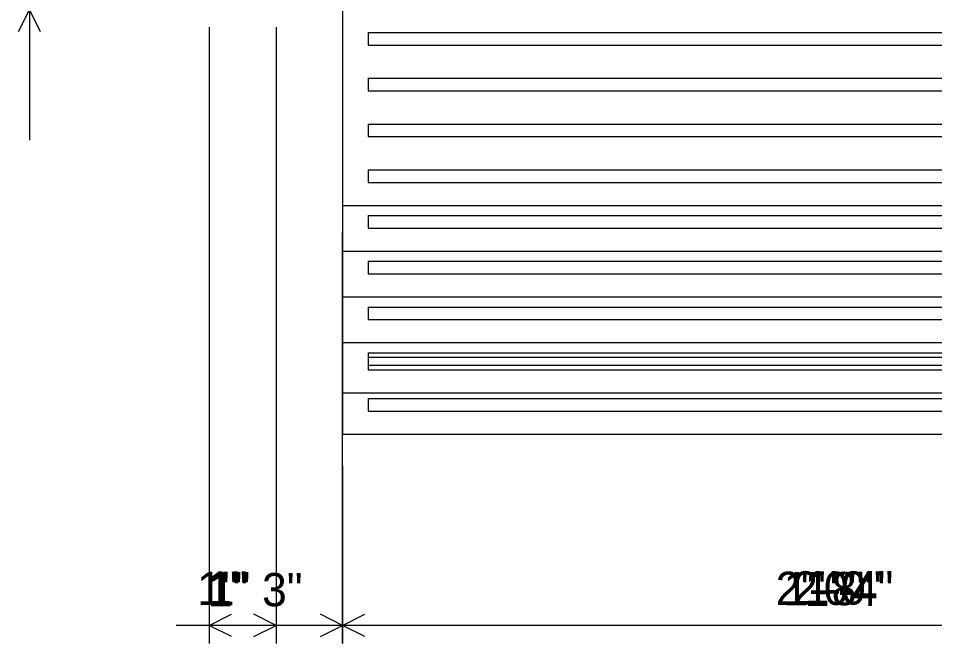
# Model space of a CAD drawing. Extents: x 997.7 to 1009.7, y 1494.3 to 1503.3.
# Drawn here: x 1000.466 to 1001.614, y 1499.262 to 1500.045 of the extents above; entities that cross this region are included whole.
import ezdxf

# ---------------------------------------------------------------- set-up
doc = ezdxf.new("R2010")
doc.units = 0
for name, color, linetype in [('Level 10', 7, 'Continuous'), ('Level 11', 7, 'Continuous'), ('Level 12', 7, 'Continuous'), ('Level 13', 7, 'Continuous'), ('Level 14', 7, 'Continuous'), ('Level 15', 7, 'Continuous'), ('Level 2', 7, 'Continuous'), ('Level 4', 7, 'Continuous'), ('Level 5', 7, 'Continuous'), ('Level 6', 7, 'Continuous'), ('Level 7', 7, 'Continuous'), ('Level 8', 7, 'Continuous'), ('Level 9', 7, 'Continuous')]:
    doc.layers.add(name, color=color, linetype=linetype)

msp = doc.modelspace()

# ---------------------------------------------------------------- linework, layer by layer
at = {"layer": 'Level 10'}
for p, q in [((1000.8725, 1499.9256), (1000.8725, 1499.7537)), ((1000.9044, 1499.7982), (1002.1738, 1499.7982)), ((1000.9044, 1499.7982), (1000.9044, 1499.7826)), ((1000.9044, 1499.7826), (1002.1738, 1499.7826)), ((1000.8725, 1499.7537), (1002.2058, 1499.7537)), ((1000.8725, 1499.2622), (1000.8725, 1499.7139))]:
    msp.add_line(p, q, dxfattribs=at)
at = {"layer": 'Level 11'}
for p, q in [((1000.8725, 1499.9256), (1000.8725, 1499.6964)), ((1000.9044, 1499.7982), (1002.1738, 1499.7982)), ((1000.9044, 1499.7982), (1000.9044, 1499.7826)), ((1000.9044, 1499.7826), (1002.1738, 1499.7826)), ((1000.9044, 1499.7409), (1002.1738, 1499.7409)), ((1000.9044, 1499.7409), (1000.9044, 1499.7253)), ((1000.9044, 1499.7253), (1002.1738, 1499.7253)), ((1000.8725, 1499.6964), (1002.2058, 1499.6964)), ((1000.8725, 1499.2622), (1000.8725, 1499.6591))]:
    msp.add_line(p, q, dxfattribs=at)
at = {"layer": 'Level 12'}
for p, q in [((1000.8725, 1499.9256), (1000.8725, 1499.6391)), ((1000.9044, 1499.7982), (1002.1738, 1499.7982)), ((1000.9044, 1499.7982), (1000.9044, 1499.7826)), ((1000.9044, 1499.7826), (1002.1738, 1499.7826)), ((1000.9044, 1499.7409), (1002.1738, 1499.7409)), ((1000.9044, 1499.7409), (1000.9044, 1499.7253)), ((1000.9044, 1499.7253), (1002.1738, 1499.7253)), ((1000.9044, 1499.6836), (1002.1738, 1499.6836)), ((1000.9044, 1499.6836), (1000.9044, 1499.668)), ((1000.9044, 1499.668), (1002.1738, 1499.668)), ((1000.8725, 1499.6391), (1002.2058, 1499.6391)), ((1000.8725, 1499.2622), (1000.8725, 1499.6085))]:
    msp.add_line(p, q, dxfattribs=at)
at = {"layer": 'Level 13'}
for p, q in [((1000.8725, 1499.9256), (1000.8725, 1499.5764)), ((1000.9044, 1499.7982), (1002.1738, 1499.7982)), ((1000.9044, 1499.7982), (1000.9044, 1499.7826)), ((1000.9044, 1499.7826), (1002.1738, 1499.7826)), ((1000.9044, 1499.7409), (1002.1738, 1499.7409)), ((1000.9044, 1499.7409), (1000.9044, 1499.7253)), ((1000.9044, 1499.7253), (1002.1738, 1499.7253)), ((1000.9044, 1499.6836), (1002.1738, 1499.6836)), ((1000.9044, 1499.6836), (1000.9044, 1499.668)), ((1000.9044, 1499.668), (1002.1738, 1499.668)), ((1000.9044, 1499.6208), (1002.1738, 1499.6208)), ((1000.9044, 1499.6208), (1000.9044, 1499.6052)), ((1000.9044, 1499.6052), (1002.1738, 1499.6052)), ((1000.8725, 1499.5764), (1002.2058, 1499.5764)), ((1000.8725, 1499.2622), (1000.8725, 1499.5413))]:
    msp.add_line(p, q, dxfattribs=at)
at = {"layer": 'Level 14'}
for p, q in [((1000.8725, 1499.9256), (1000.8725, 1499.5246)), ((1000.9044, 1499.7982), (1002.1738, 1499.7982)), ((1000.9044, 1499.7982), (1000.9044, 1499.7826)), ((1000.9044, 1499.7826), (1002.1738, 1499.7826)), ((1000.9044, 1499.7409), (1002.1738, 1499.7409)), ((1000.9044, 1499.7409), (1000.9044, 1499.7253)), ((1000.9044, 1499.7253), (1002.1738, 1499.7253)), ((1000.9044, 1499.6836), (1002.1738, 1499.6836)), ((1000.9044, 1499.6836), (1000.9044, 1499.668)), ((1000.9044, 1499.668), (1002.1738, 1499.668)), ((1000.9044, 1499.6263), (1002.1738, 1499.6263)), ((1000.9044, 1499.6263), (1000.9044, 1499.6107)), ((1000.9044, 1499.6107), (1002.1738, 1499.6107)), ((1000.9044, 1499.569), (1002.1738, 1499.569)), ((1000.9044, 1499.569), (1000.9044, 1499.5534)), ((1000.9044, 1499.5534), (1002.1738, 1499.5534)), ((1000.8725, 1499.5246), (1002.2058, 1499.5246)), ((1000.8725, 1499.4849), (1000.8725, 1499.2622))]:
    msp.add_line(p, q, dxfattribs=at)
at = {"layer": 'Level 15'}
for p, q in [((1000.7055, 1500.0341), (1000.7055, 1499.2622)), ((1000.8725, 1499.2851), (1000.7055, 1499.2851))]:
    msp.add_line(p, q, dxfattribs=at)
for points in [[(1000.7333, 1499.2712), (1000.7055, 1499.2851), (1000.7333, 1499.299)], [(1000.8448, 1499.2712), (1000.8725, 1499.2851), (1000.8448, 1499.299)]]:
    msp.add_lwpolyline(points, dxfattribs=at)
at = {"layer": 'Level 2'}
for p, q in [((1000.4803, 1500.0562), (1000.4803, 1499.8927)), ((1000.8725, 1500.0562), (1000.8725, 1499.9256)), ((1000.9044, 1500.0273), (1002.1738, 1500.0273)), ((1000.9044, 1500.0273), (1000.9044, 1500.0117)), ((1000.9044, 1500.0117), (1002.1738, 1500.0117)), ((1000.9044, 1499.9701), (1002.1738, 1499.9701)), ((1000.9044, 1499.9701), (1000.9044, 1499.9544)), ((1000.9044, 1499.9544), (1002.1738, 1499.9544)), ((1000.9044, 1499.9128), (1002.1738, 1499.9128)), ((1000.9044, 1499.9128), (1000.9044, 1499.8971)), ((1000.9044, 1499.8971), (1002.1738, 1499.8971)), ((1000.9044, 1499.8555), (1002.1738, 1499.8555)), ((1000.9044, 1499.8555), (1000.9044, 1499.8398)), ((1000.9044, 1499.8398), (1002.1738, 1499.8398)), ((1002.2058, 1499.2851), (1000.8725, 1499.2851))]:
    msp.add_line(p, q, dxfattribs=at)
for points in [[(1000.4942, 1500.0284), (1000.4803, 1500.0562), (1000.4663, 1500.0284)], [(1000.9003, 1499.2712), (1000.8725, 1499.2851), (1000.9003, 1499.299)]]:
    msp.add_lwpolyline(points, dxfattribs=at)
at = {"layer": 'Level 4'}
for p, q in [((1000.7892, 1500.0341), (1000.7892, 1499.2622)), ((1000.7892, 1499.2851), (1000.6642, 1499.2851))]:
    msp.add_line(p, q, dxfattribs=at)
msp.add_lwpolyline([(1000.7614, 1499.2712), (1000.7892, 1499.2851), (1000.7614, 1499.299)], dxfattribs=at)
at = {"layer": 'Level 5'}
for p, q in [((1000.7892, 1500.0341), (1000.7892, 1499.2622)), ((1000.7892, 1499.2851), (1000.6642, 1499.2851))]:
    msp.add_line(p, q, dxfattribs=at)
msp.add_lwpolyline([(1000.7614, 1499.2712), (1000.7892, 1499.2851), (1000.7614, 1499.299)], dxfattribs=at)
at = {"layer": 'Level 6'}
for p, q in [((1000.7892, 1500.0341), (1000.7892, 1499.2622)), ((1000.7892, 1499.2851), (1000.6642, 1499.2851))]:
    msp.add_line(p, q, dxfattribs=at)
msp.add_lwpolyline([(1000.7614, 1499.2712), (1000.7892, 1499.2851), (1000.7614, 1499.299)], dxfattribs=at)
at = {"layer": 'Level 7'}
for p, q in [((1000.7892, 1500.0341), (1000.7892, 1499.2622)), ((1000.7892, 1499.2851), (1000.6642, 1499.2851))]:
    msp.add_line(p, q, dxfattribs=at)
msp.add_lwpolyline([(1000.7614, 1499.2712), (1000.7892, 1499.2851), (1000.7614, 1499.299)], dxfattribs=at)
at = {"layer": 'Level 8'}
for p, q in [((1000.7892, 1500.0341), (1000.7892, 1499.2622)), ((1000.7892, 1499.2851), (1000.6642, 1499.2851))]:
    msp.add_line(p, q, dxfattribs=at)
msp.add_lwpolyline([(1000.7614, 1499.2712), (1000.7892, 1499.2851), (1000.7614, 1499.299)], dxfattribs=at)
at = {"layer": 'Level 9'}
for p, q in [((1000.8725, 1499.9256), (1000.8725, 1499.811)), ((1000.8725, 1499.811), (1002.2058, 1499.811)), ((1000.8725, 1499.2622), (1000.8725, 1499.7775))]:
    msp.add_line(p, q, dxfattribs=at)

# ---------------------------------------------------------------- texts
at = {"layer": 'Level 15'}
for s, p in [('2\'-0" ', (1001.4365, 1499.3111)), ('3" ', (1000.7716, 1499.309))]:
    msp.add_text(s, height=0.04167, dxfattribs=at).set_placement(p)
at = {"layer": 'Level 4'}
for s, p in [('1\'-4" ', (1001.4512, 1499.3116)), ('1" ', (1000.6903, 1499.3105))]:
    msp.add_text(s, height=0.04167, dxfattribs=at).set_placement(p)
at = {"layer": 'Level 5'}
for s, p in [('1" ', (1000.7035, 1499.3091)), ('1\'-4" ', (1001.4512, 1499.3093))]:
    msp.add_text(s, height=0.04167, dxfattribs=at).set_placement(p)
at = {"layer": 'Level 6'}
for s, p in [('1" ', (1000.7062, 1499.3102)), ('1\'-8" ', (1001.4249, 1499.3103))]:
    msp.add_text(s, height=0.04167, dxfattribs=at).set_placement(p)
at = {"layer": 'Level 7'}
for s, p in [('2\'-0" ', (1001.4149, 1499.3106)), ('1" ', (1000.7027, 1499.3109))]:
    msp.add_text(s, height=0.04167, dxfattribs=at).set_placement(p)
at = {"layer": 'Level 8'}
for s, p in [('2\'-0" ', (1001.4149, 1499.3106)), ('1" ', (1000.7027, 1499.3105))]:
    msp.add_text(s, height=0.04167, dxfattribs=at).set_placement(p)

doc.saveas('drawing.dxf')
